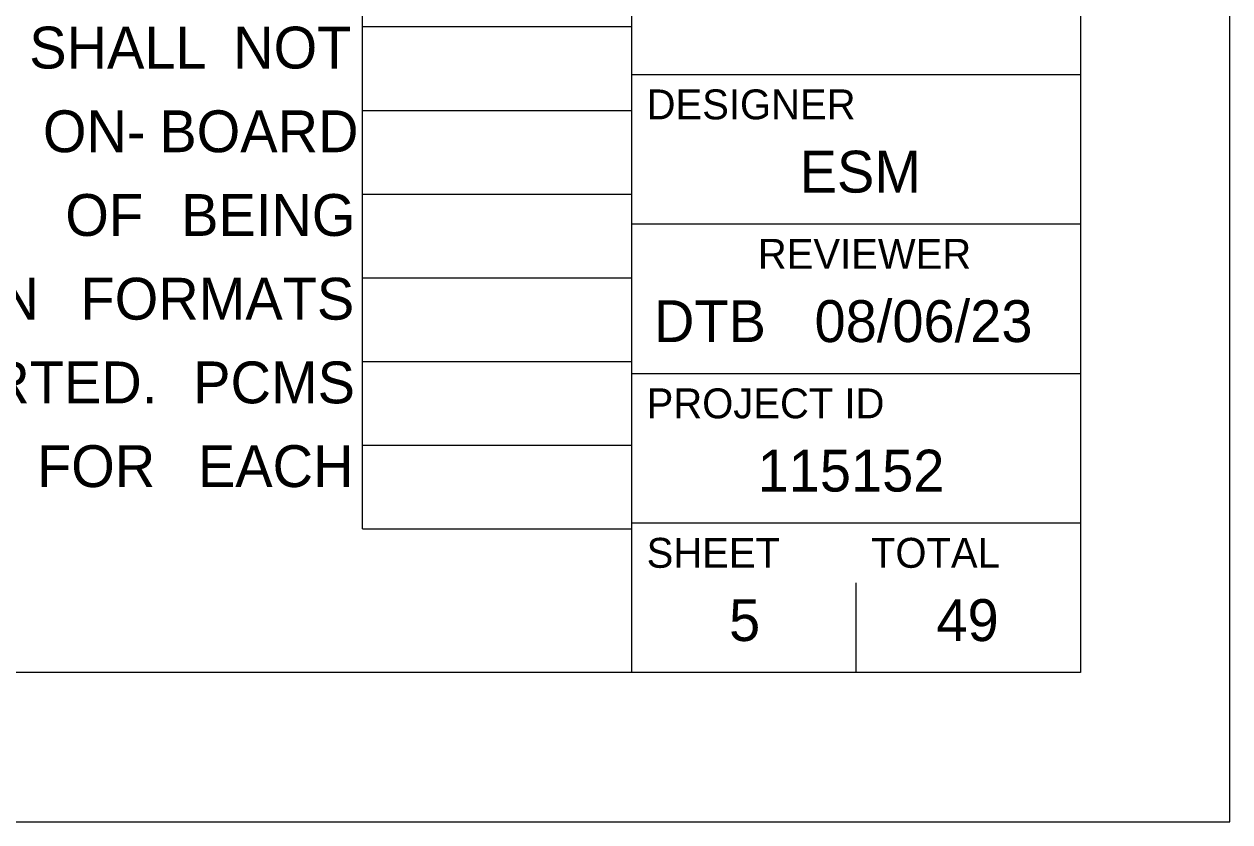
# Model space of a CAD drawing. Extents: x 0 to 34, y 0 to 22.
# Drawn here: x 29.969 to 34, y 0 to 2.669 of the extents above; entities that cross this region are included whole.
import ezdxf

# ---------------------------------------------------------------- set-up
doc = ezdxf.new("R2010")
doc.units = 0
for name, color, linetype in [('SH_Border', 7, 'Continuous'), ('SH_Cut_Line', 7, 'Continuous'), ('SH_Data', 7, 'Continuous'), ('SH_Text', 7, 'Continuous')]:
    doc.layers.add(name, color=color, linetype=linetype)

msp = doc.modelspace()

# ---------------------------------------------------------------- linework, layer by layer
at = {"layer": 'SH_Border'}
for p, q in [((32, 0.5), (32, 21.5)), ((32, 2.5), (33.5, 2.5)), ((32, 2), (33.5, 2)), ((32, 1.5), (33.5, 1.5)), ((32, 1), (33.5, 1))]:
    msp.add_line(p, q, dxfattribs=at)
msp.add_lwpolyline([(1.5, 21.5), (33.5, 21.5), (33.5, 0.5), (1.5, 0.5)], close=True, dxfattribs=at)
at = {"layer": 'SH_Cut_Line'}
msp.add_lwpolyline([(0, 0), (34, 0), (34, 22), (0, 22)], close=True, dxfattribs=at)
at = {"layer": 'SH_Data'}
for p, q in [((31.1, 0.98), (31.1, 21.14)), ((32, 0.98), (32, 21.14)), ((31.1, 2.66), (32, 2.66)), ((31.1, 2.38), (32, 2.38)), ((31.1, 2.1), (32, 2.1)), ((31.1, 1.82), (32, 1.82)), ((31.1, 1.54), (32, 1.54)), ((31.1, 1.26), (32, 1.26)), ((31.1, 0.98), (32, 0.98)), ((32.75, 0.5), (32.75, 0.8)), ((32.375, 0.675), (32.375, 0.675))]:
    msp.add_line(p, q, dxfattribs=at)

# ---------------------------------------------------------------- texts
for s, height, p in [('DESIGNER', 0.1, (32.05, 2.35)), ('ESM', 0.14, (32.5615, 2.105)), ('REVIEWER', 0.1, (32.4218, 1.85)), ('DTB', 0.14, (32.0744, 1.605)), ('08/06/23', 0.14, (32.6113, 1.605)), ('PROJECT ID', 0.1, (32.05, 1.35)), ('115152', 0.14, (32.4209, 1.105)), ('SHEET', 0.1, (32.05, 0.85)), ('TOTAL', 0.1, (32.8, 0.85)), ('5', 0.14, (32.3256, 0.605)), ('49', 0.14, (33.0188, 0.605))]:
    msp.add_text(s, height=height, dxfattribs=at).set_placement(p)
at = {"layer": 'SH_Text'}
for s, p in [('SHALL ', (29.9858, 2.52)), ('NOT ', (30.6677, 2.52)), ('ON-', (30.0316, 2.24)), ('BOARD ', (30.4208, 2.24)), ('OF ', (30.1064, 1.96)), ('BEING ', (30.4936, 1.96)), ('PRESENTATION ', (28.5613, 1.68)), ('FORMATS ', (30.1572, 1.68)), ('SUPPORTED. ', (29.1968, 1.4)), ('PCMS ', (30.5339, 1.4)), ('FOR ', (30.0118, 1.12)), ('EACH ', (30.5497, 1.12))]:
    msp.add_text(s, height=0.14, dxfattribs=at).set_placement(p)

doc.saveas('drawing.dxf')
